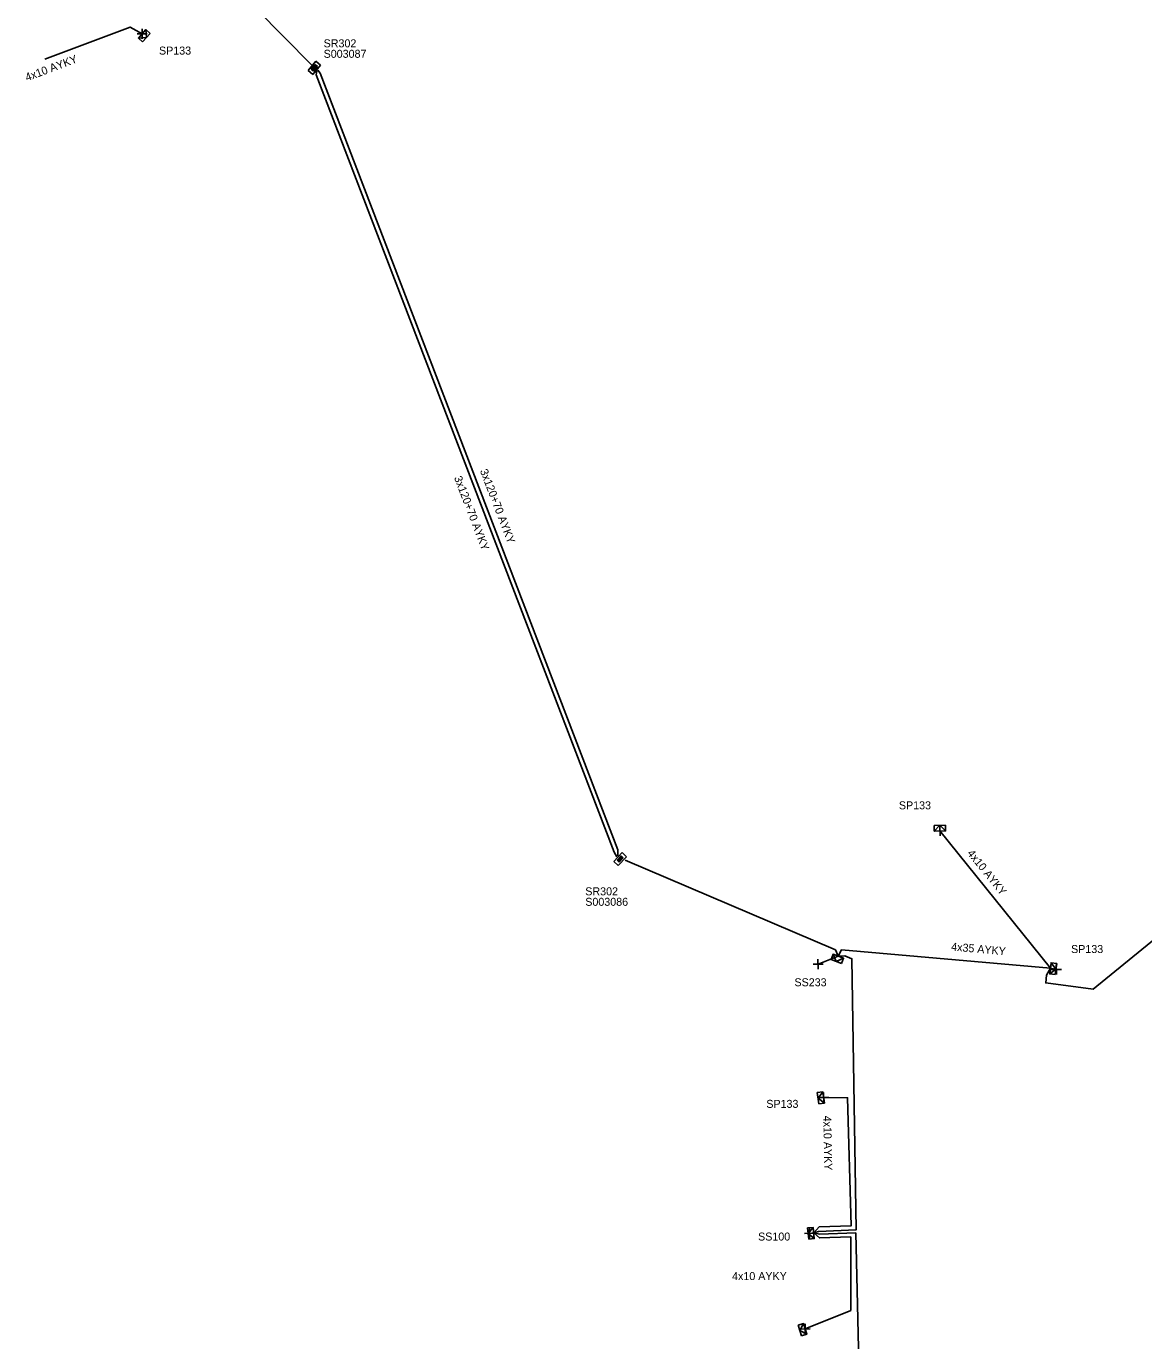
# Model space of a CAD drawing. Extents: x -762503 to -762212, y -1153994 to -1153331.
# Drawn here: x -762502.3 to -762363.4, y -1153662.2 to -1153498.9 of the extents above; entities that cross this region are included whole.
import ezdxf

# ---------------------------------------------------------------- set-up
doc = ezdxf.new("R2010")
doc.units = 0
for name, color, linetype in [('Vrstva 28', 7, 'Continuous'), ('Vrstva 29', 7, 'Continuous'), ('Vrstva 30', 7, 'Continuous'), ('Vrstva 31', 7, 'Continuous'), ('Vrstva 33', 7, 'Continuous'), ('Vrstva 34', 7, 'Continuous'), ('Vrstva 5', 7, 'Continuous'), ('Vrstva 52', 7, 'Continuous'), ('Vrstva 54', 7, 'Continuous'), ('Vrstva 59', 7, 'Continuous'), ('Vrstva 6', 7, 'Continuous')]:
    doc.layers.add(name, color=color, linetype=linetype)

msp = doc.modelspace()

# ---------------------------------------------------------------- linework, layer by layer
at = {"layer": 'Vrstva 28'}
for points in [[(-762466.311, -1153503.247), (-762467.275, -1153504.396)], [(-762466.406, -1153503.654), (-762466.884, -1153504.224)], [(-762466.4, -1153503.72), (-762466.817, -1153504.218)], [(-762466.394, -1153503.787), (-762466.751, -1153504.212)], [(-762466.701, -1153504.878), (-762465.737, -1153503.729)], [(-762466.388, -1153503.853), (-762466.684, -1153504.206)], [(-762466.379, -1153503.915), (-762466.621, -1153504.205)], [(-762466.612, -1153504.267), (-762466.316, -1153503.914)], [(-762466.606, -1153504.334), (-762466.249, -1153503.908)], [(-762466.6, -1153504.4), (-762466.183, -1153503.902)], [(-762466.594, -1153504.467), (-762466.116, -1153503.897)], [(-762466.116, -1153503.897), (-762466.406, -1153503.654)], [(-762466.183, -1153503.902), (-762466.4, -1153503.72)], [(-762466.249, -1153503.908), (-762466.394, -1153503.787)], [(-762466.316, -1153503.914), (-762466.388, -1153503.853)], [(-762465.737, -1153503.729), (-762466.311, -1153503.247)], [(-762467.275, -1153504.396), (-762466.701, -1153504.878)], [(-762466.884, -1153504.224), (-762466.594, -1153504.467)], [(-762466.817, -1153504.218), (-762466.6, -1153504.4)], [(-762466.751, -1153504.212), (-762466.606, -1153504.334)], [(-762466.684, -1153504.206), (-762466.612, -1153504.267)], [(-762428.239, -1153601.578), (-762429.262, -1153602.675)], [(-762427.691, -1153602.089), (-762428.239, -1153601.578)], [(-762429.262, -1153602.675), (-762428.714, -1153603.186)], [(-762428.367, -1153601.983), (-762428.875, -1153602.527)], [(-762428.875, -1153602.527), (-762428.598, -1153602.785)], [(-762428.365, -1153602.05), (-762428.808, -1153602.525)], [(-762428.808, -1153602.525), (-762428.601, -1153602.718)], [(-762428.363, -1153602.117), (-762428.741, -1153602.523)], [(-762428.741, -1153602.523), (-762428.603, -1153602.652)], [(-762428.714, -1153603.186), (-762427.691, -1153602.089)], [(-762428.36, -1153602.183), (-762428.674, -1153602.52)], [(-762428.674, -1153602.52), (-762428.605, -1153602.585)], [(-762428.612, -1153602.522), (-762428.354, -1153602.246)], [(-762428.605, -1153602.585), (-762428.291, -1153602.248)], [(-762428.603, -1153602.652), (-762428.224, -1153602.245)], [(-762428.601, -1153602.718), (-762428.158, -1153602.243)], [(-762428.598, -1153602.785), (-762428.091, -1153602.241)], [(-762428.091, -1153602.241), (-762428.367, -1153601.983)], [(-762428.158, -1153602.243), (-762428.365, -1153602.05)], [(-762428.224, -1153602.245), (-762428.363, -1153602.117)], [(-762428.291, -1153602.248), (-762428.36, -1153602.183)]]:
    msp.add_lwpolyline(points, dxfattribs=at)
at = {"layer": 'Vrstva 31'}
for points in [[(-762487.84, -1153500.821), (-762488.36, -1153500.353), (-762487.423, -1153499.312), (-762486.903, -1153499.781)], [(-762487.371, -1153500.301), (-762488.36, -1153500.353)], [(-762487.84, -1153500.821), (-762486.903, -1153499.781)], [(-762487.371, -1153500.301), (-762487.423, -1153499.312)], [(-762388.05, -1153598.178), (-762389.45, -1153598.202)], [(-762388.05, -1153598.178), (-762388.038, -1153598.877), (-762389.437, -1153598.902), (-762389.45, -1153598.202)], [(-762388.75, -1153598.19), (-762389.437, -1153598.902)], [(-762388.75, -1153598.19), (-762388.038, -1153598.877)], [(-762402.277, -1153614.862), (-762402.026, -1153614.208), (-762400.719, -1153614.71), (-762400.97, -1153615.363)], [(-762402.277, -1153614.862), (-762400.97, -1153615.363)], [(-762401.624, -1153615.112), (-762402.026, -1153614.208)], [(-762401.624, -1153615.112), (-762400.719, -1153614.71)], [(-762374.4, -1153616.743), (-762375.095, -1153616.657), (-762374.924, -1153615.268), (-762374.229, -1153615.353)], [(-762374.315, -1153616.048), (-762375.095, -1153616.657)], [(-762374.315, -1153616.048), (-762374.924, -1153615.268)], [(-762374.4, -1153616.743), (-762374.229, -1153615.353)], [(-762403.981, -1153631.411), (-762403.288, -1153631.314), (-762403.093, -1153632.7), (-762403.787, -1153632.798)], [(-762403.884, -1153632.104), (-762403.288, -1153631.314)], [(-762403.981, -1153631.411), (-762403.787, -1153632.798)], [(-762403.884, -1153632.104), (-762403.093, -1153632.7)], [(-762405.2, -1153648.224), (-762404.503, -1153648.151), (-762404.357, -1153649.543), (-762405.053, -1153649.616)], [(-762405.2, -1153648.224), (-762405.053, -1153649.616)], [(-762405.126, -1153648.92), (-762404.503, -1153648.151)], [(-762405.126, -1153648.92), (-762404.357, -1153649.543)], [(-762406.365, -1153660.302), (-762405.696, -1153660.098), (-762405.287, -1153661.437), (-762405.956, -1153661.641)], [(-762406.365, -1153660.302), (-762405.956, -1153661.641)], [(-762406.161, -1153660.972), (-762405.696, -1153660.098)], [(-762406.161, -1153660.972), (-762405.287, -1153661.437)]]:
    msp.add_lwpolyline(points, dxfattribs=at)
at = {"layer": 'Vrstva 34'}
for points in [[(-762488.515, -1153499.841), (-762487.265, -1153499.819)], [(-762487.879, -1153500.455), (-762487.901, -1153499.205)], [(-762388.729, -1153599.515), (-762388.751, -1153598.265)], [(-762389.365, -1153598.901), (-762388.115, -1153598.879)], [(-762403.879, -1153616.065), (-762403.901, -1153614.815)], [(-762404.515, -1153615.451), (-762403.265, -1153615.429)], [(-762374.895, -1153616.121), (-762373.645, -1153616.099)], [(-762374.259, -1153616.735), (-762374.281, -1153615.485)], [(-762403.815, -1153632.021), (-762402.565, -1153631.999)], [(-762403.179, -1153632.635), (-762403.201, -1153631.385)], [(-762405.585, -1153648.911), (-762404.335, -1153648.889)], [(-762404.949, -1153649.525), (-762404.971, -1153648.275)], [(-762406.115, -1153660.781), (-762404.865, -1153660.759)], [(-762405.479, -1153661.395), (-762405.501, -1153660.145)]]:
    msp.add_lwpolyline(points, dxfattribs=at)
at = {"layer": 'Vrstva 5'}
for points in [[(-762466.85, -1153503.67), (-762483.97, -1153486.34), (-762494.21, -1153494.09), (-762494.82, -1153494)], [(-762428.88, -1153602.09), (-762429.21, -1153601.51), (-762466.25, -1153504.94), (-762466.17, -1153504.43)], [(-762428.79, -1153602), (-762428.79, -1153601.25), (-762465.79, -1153504.73), (-762466.08, -1153504.33)], [(-762427.88, -1153602.5), (-762401.72, -1153613.66), (-762401.37, -1153614.46)], [(-762401.37, -1153614.46), (-762400.97, -1153613.65), (-762375.01, -1153615.96), (-762375.49, -1153616.82), (-762375.58, -1153617.77), (-762369.69, -1153618.53), (-762352.02, -1153604.12)], [(-762401.37, -1153614.46), (-762400.57, -1153614.41), (-762399.68, -1153614.77), (-762399.13, -1153648.45), (-762403.85, -1153648.67), (-762404.43, -1153648.85), (-762403.69, -1153649.01), (-762399.2, -1153648.85), (-762398.88, -1153663.17), (-762398.84, -1153664.54), (-762376.56, -1153683.82), (-762376.7, -1153685.06), (-762375.27, -1153683.69), (-762342.71, -1153696.28), (-762329.6, -1153709.89), (-762330.45, -1153711.52), (-762329.56, -1153711.08), (-762316.93, -1153716.36), (-762288.76, -1153722.92), (-762288.67, -1153723.88), (-762288.09, -1153723.01), (-762237.01, -1153735.42), (-762233.07, -1153748.45), (-762233.31, -1153749.42)]]:
    msp.add_lwpolyline(points, dxfattribs=at)
at = {"layer": 'Vrstva 52'}
for points in [[(-762500, -1153503), (-762489.39, -1153498.99), (-762487.89, -1153499.83)], [(-762375.01, -1153615.96), (-762388.74, -1153598.89)], [(-762404.43, -1153648.85), (-762403.76, -1153648.09), (-762399.77, -1153647.96), (-762400.22, -1153632.05), (-762403.19, -1153632.01)], [(-762404.43, -1153648.85), (-762403.72, -1153649.47), (-762399.82, -1153649.34), (-762399.82, -1153658.47), (-762405.49, -1153660.77)]]:
    msp.add_lwpolyline(points, dxfattribs=at)
at = {"layer": 'Vrstva 59'}
for points in [[(-762401.37, -1153614.46), (-762403.89, -1153615.44)], [(-762375.01, -1153615.96), (-762374.27, -1153616.11)], [(-762404.43, -1153648.85), (-762404.96, -1153648.9)]]:
    msp.add_lwpolyline(points, dxfattribs=at)

# ---------------------------------------------------------------- texts
at = {"layer": 'Vrstva 29'}
for s, p in [('S003087', (-762465.34, -1153502.81)), ('S003086', (-762432.82, -1153608.19))]:
    msp.add_text(s, height=0.9943, dxfattribs=at).set_placement(p)
at = {"layer": 'Vrstva 30'}
for p in [(-762465.34, -1153501.51), (-762432.82, -1153606.89)]:
    msp.add_text('SR302', height=0.9943, dxfattribs=at).set_placement(p)
at = {"layer": 'Vrstva 33'}
for s, p in [('SP133', (-762485.8, -1153502.41)), ('SP133', (-762393.84, -1153596.2)), ('SP133', (-762372.44, -1153614.06)), ('SS233', (-762406.82, -1153618.19)), ('SP133', (-762410.32, -1153633.3)), ('SS100', (-762411.34, -1153649.79))]:
    msp.add_text(s, height=0.9943, dxfattribs=at).set_placement(p)
at = {"layer": 'Vrstva 54'}
for rotation, p in [(20.71843, (-762502.21, -1153505.75)), (308.82506, (-762385.41, -1153601.69)), (271.10107, (-762403.24, -1153634.28)), (0.25794, (-762414.57, -1153654.71))]:
    msp.add_text('4x10 AYKY', height=0.9943, rotation=rotation, dxfattribs=at).set_placement(p)
at = {"layer": 'Vrstva 6'}
for s, height, rotation, p in [('3x120+70 AYKY', 0.99429, 290.97541, (-762445.93, -1153554.13)), ('3x120+70 AYKY', 0.99429, 290.98312, (-762449.15, -1153554.99)), ('4x35 AYKY', 0.9943, 354.922, (-762387.37, -1153613.74))]:
    msp.add_text(s, height=height, rotation=rotation, dxfattribs=at).set_placement(p)

doc.saveas('drawing.dxf')
